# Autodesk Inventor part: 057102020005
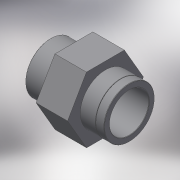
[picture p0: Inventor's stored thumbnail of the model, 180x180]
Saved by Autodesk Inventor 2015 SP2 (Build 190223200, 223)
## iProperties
Created: 2017-10
Part Number: 057102020005
Material: Generic
Description: PLASSON NOT ACTIVE- AD. SOCKET REINF.PVC 20-1/2
Document SubType Name: Modeling
Designer: KIM
Density: 1 g/cm^3
Appearance: Default
Author: KIM
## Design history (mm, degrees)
derived "057102.ipt"
feature "Solid1::057102.ipt"
tag "TaggingFeature1"
body "Solid1"
other parameters: "d0" = 36, "d3" = 18.631, "d4" = 18, "d5" = 16, "d6" = 17, "d7" = 24, "d8" = 23, "d10" = 11.9, "d13" = 0, "d14" = 0.2, "d15" = 12, "d16" = 4.25, "d17" = 24, "d18" = 0.1, "G_" = 18.631, "B_" = 12, "l_" = 16, "lt_" = 17, "H_" = 36
